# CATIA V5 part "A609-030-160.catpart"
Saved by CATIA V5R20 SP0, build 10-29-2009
Part number: A609-030-160
Source: Unknown
Property "ARTICLENO": "A609-030-160"
Property "B": "30.000"
Property "BOMINFO": "A609-030-160"
Property "CODE": "A609-030-160"
Property "D": "20.000"
Property "D1": "13.500"
Property "FORM": "A"
Property "L": "160.000"
Property "L1": "25.000"
Property "L2": "110.000"
Property "LINA": "A609-030-160"
Property "NB": "A609-030-160"
Property "NBSYN": "$CODE."
Property "NN": "A609"
Property "NT": "VDI 3357 E-Type Wear Plates, self-lubricating"
Property "S": "30.000"
Property "SUPPLIER": "CF"
Property "T": "13.000"
Property "W": "60.000"
Bounding box of the stored display mesh (mm): x 0 to 160, y 0 to 30, z 0 to 60
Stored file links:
  C:\Users\Utente\Desktop\3D files A609\A609-030-160.catpart
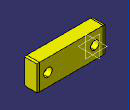
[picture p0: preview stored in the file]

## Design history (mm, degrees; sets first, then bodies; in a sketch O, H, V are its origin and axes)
Body1 "Geometry.1" (main body)
  Solid1 "A609-030-160.catpart": solid without history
